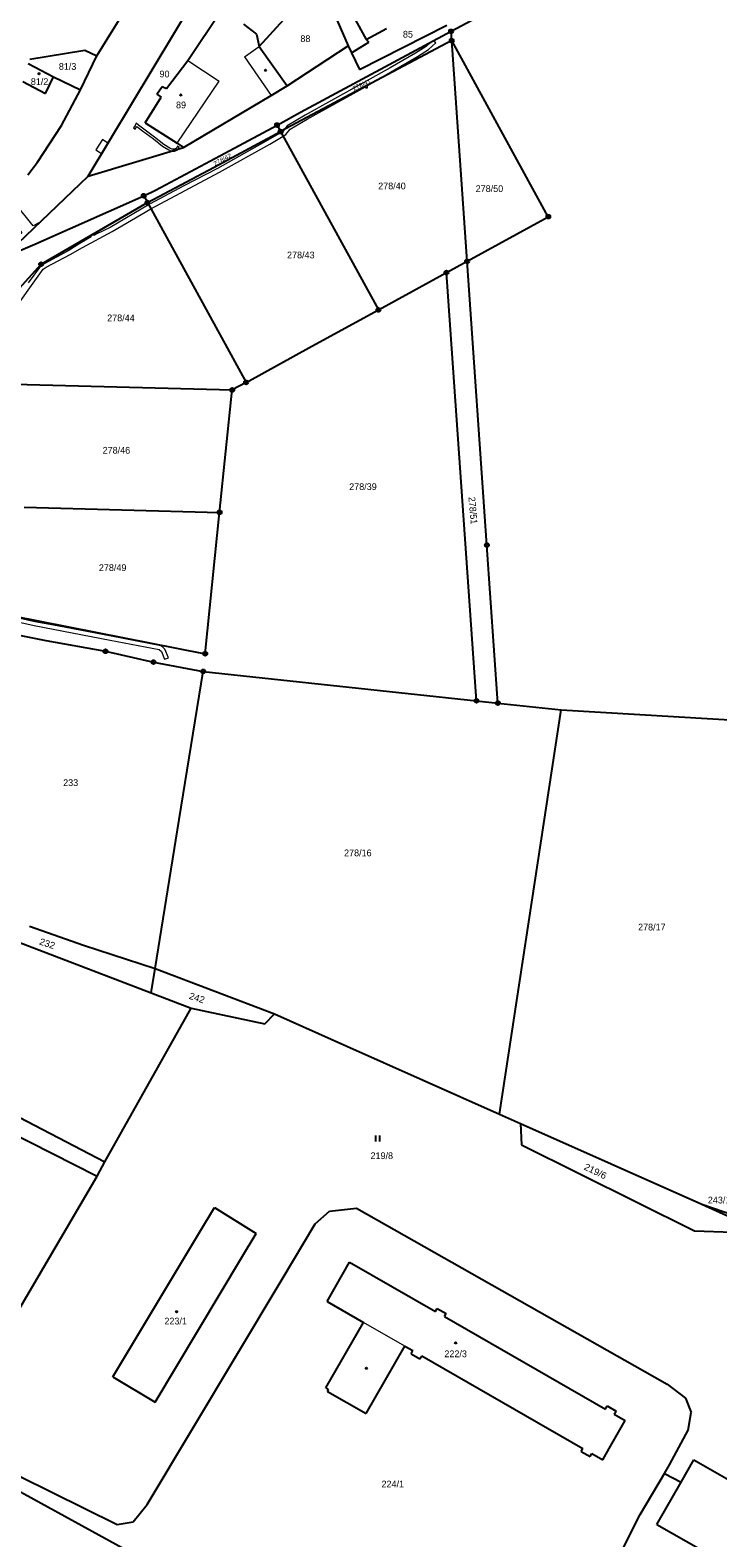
# Model space of a CAD drawing. Extents: x -633485 to -630509, y -1112692 to -1108818.
# Drawn here: x -631743.5 to -631569.8, y -1111932.7 to -1111552 of the extents above; entities that cross this region are included whole.
import ezdxf
from ezdxf.enums import TextEntityAlignment as Align

# ---------------------------------------------------------------- set-up
doc = ezdxf.new("R2010")
doc.units = 0
doc.header["$LTSCALE"] = 0.68
for name, color, linetype, lineweight in [('1', 7, 'Continuous', 25), ('13', 7, 'Continuous', 13), ('3', 7, 'Continuous', 25), ('4', 7, 'Continuous', 13), ('5', 7, 'Continuous', 25), ('8', 7, 'Continuous', 25)]:
    doc.layers.add(name, color=color, linetype=linetype, lineweight=lineweight)
doc.layers.add('2', color=7, linetype='Continuous')

msp = doc.modelspace()

# ---------------------------------------------------------------- linework, layer by layer
at = {"layer": '1'}
for p, q in [((-631726.65, -1111558.43), (-631645.19, -1111427.57)), ((-631637.17, -1111552.27), (-631591.93, -1111527.94)), ((-631685.62, -1111556.11), (-631670.36, -1111539.33)), ((-631670.36, -1111539.33), (-631663.19, -1111555.95)), ((-631665.55, -1111541.61), (-631658.58, -1111554.35)), ((-631728.81, -1111588.83), (-631701.37, -1111543.15)), ((-631703.67, -1111559.63), (-631695.16, -1111546.91)), ((-631689.61, -1111550.49), (-631686.3, -1111552.96)), ((-631686.3, -1111552.96), (-631685.62, -1111556.11)), ((-631675.15, -1111572.69), (-631637.17, -1111552.27)), ((-631660.31, -1111561.93), (-631638.26, -1111550.73)), ((-631658.58, -1111554.35), (-631653.51, -1111551.58)), ((-631658.58, -1111554.35), (-631657.97, -1111554.99)), ((-631637.01, -1111554.62), (-631637.17, -1111552.27)), ((-631743.57, -1111559.29), (-631729.66, -1111557.04)), ((-631729.66, -1111557.04), (-631726.65, -1111558.43)), ((-631685.62, -1111556.11), (-631678.57, -1111566.06)), ((-631637.01, -1111554.62), (-631680.21, -1111577.6)), ((-631678.57, -1111566.06), (-631663.19, -1111555.95)), ((-631663.19, -1111555.95), (-631662.33, -1111557.72)), ((-631662.33, -1111557.72), (-631657.97, -1111554.99)), ((-631662.33, -1111557.72), (-631660.31, -1111561.93)), ((-631633.12, -1111610.34), (-631637.01, -1111554.62)), ((-631612.61, -1111599.08), (-631637.01, -1111554.62)), ((-631743.97, -1111560.4), (-631737.55, -1111563.79)), ((-631730.72, -1111567.08), (-631726.65, -1111558.43)), ((-631709.03, -1111566.73), (-631703.67, -1111559.63)), ((-631745.34, -1111564.91), (-631739.54, -1111567.99)), ((-631739.54, -1111567.99), (-631737.55, -1111563.79)), ((-631737.55, -1111563.79), (-631730.72, -1111567.08)), ((-631735.51, -1111576.09), (-631730.72, -1111567.08)), ((-631714.38, -1111575.34), (-631710.39, -1111568.89)), ((-631711.46, -1111568.11), (-631710.14, -1111566.2)), ((-631711.46, -1111568.11), (-631710.39, -1111568.89)), ((-631710.14, -1111566.2), (-631709.03, -1111566.73)), ((-631704.71, -1111581.6), (-631682.58, -1111568.49)), ((-631682.58, -1111568.49), (-631678.57, -1111566.06)), ((-631681.12, -1111575.94), (-631675.15, -1111572.69)), ((-631741.6, -1111585.3), (-631735.51, -1111576.09)), ((-631714.38, -1111575.34), (-631706.32, -1111580.53)), ((-631681.12, -1111575.94), (-631680.21, -1111577.6)), ((-631706.32, -1111580.53), (-631704.71, -1111581.6)), ((-631697.03, -1111586.55), (-631680.21, -1111577.6)), ((-631680.21, -1111577.6), (-631655.5, -1111622.62)), ((-631728.81, -1111588.83), (-631704.71, -1111581.6)), ((-631744.02, -1111588.52), (-631741.6, -1111585.3)), ((-631713.85, -1111595.51), (-631697.03, -1111586.55)), ((-631750.36, -1111609.45), (-631728.81, -1111588.83)), ((-631714.78, -1111593.81), (-631711.8, -1111592.4)), ((-631742.31, -1111606), (-631714.78, -1111593.81)), ((-631714.78, -1111593.81), (-631713.85, -1111595.51)), ((-631713.85, -1111595.51), (-631688.93, -1111640.92)), ((-631633.12, -1111610.34), (-631612.61, -1111599.08)), ((-631750.36, -1111609.45), (-631742.31, -1111606)), ((-631638.34, -1111613.2), (-631633.12, -1111610.34)), ((-631628.12, -1111682.02), (-631633.12, -1111610.34)), ((-631655.5, -1111622.62), (-631638.34, -1111613.2)), ((-631630.76, -1111721.34), (-631638.34, -1111613.2)), ((-631672.29, -1111631.81), (-631655.5, -1111622.62)), ((-631688.93, -1111640.92), (-631672.29, -1111631.81)), ((-631750.72, -1111641.28), (-631692.44, -1111642.84)), ((-631688.93, -1111640.92), (-631692.44, -1111642.84)), ((-631695.61, -1111673.75), (-631692.44, -1111642.84)), ((-631744.99, -1111672.46), (-631695.61, -1111673.75)), ((-631699.26, -1111709.45), (-631695.61, -1111673.75)), ((-631625.34, -1111721.92), (-631628.12, -1111682.02)), ((-631747.8, -1111699.86), (-631699.26, -1111709.45)), ((-631748.3, -1111704.38), (-631739.51, -1111706.11)), ((-631739.51, -1111706.11), (-631724.44, -1111708.84)), ((-631724.44, -1111708.84), (-631712.31, -1111711.57)), ((-631712.31, -1111711.57), (-631699.75, -1111713.93)), ((-631705.81, -1111751.28), (-631699.75, -1111713.93)), ((-631699.75, -1111713.93), (-631630.76, -1111721.34)), ((-631630.76, -1111721.34), (-631625.34, -1111721.92)), ((-631625.34, -1111721.92), (-631609.33, -1111723.64)), ((-631624.97, -1111825.7), (-631609.33, -1111723.64)), ((-631609.33, -1111723.64), (-631547.66, -1111727.31)), ((-631711.92, -1111788.97), (-631705.81, -1111751.28)), ((-631772.03, -1111772.41), (-631712.92, -1111795.09)), ((-631743.6, -1111778.23), (-631729.98, -1111783.03)), ((-631729.98, -1111783.03), (-631711.92, -1111788.97)), ((-631712.92, -1111795.09), (-631711.92, -1111788.97)), ((-631711.92, -1111788.97), (-631681.77, -1111800.39)), ((-631712.92, -1111795.09), (-631702.83, -1111798.96)), ((-631724.6, -1111837.74), (-631702.83, -1111798.96)), ((-631702.83, -1111798.96), (-631684.21, -1111802.9)), ((-631684.21, -1111802.9), (-631681.77, -1111800.39)), ((-631681.77, -1111800.39), (-631663.5, -1111808.53)), ((-631783.6, -1111807.07), (-631724.6, -1111837.74)), ((-631663.5, -1111808.53), (-631624.97, -1111825.7)), ((-631624.97, -1111825.7), (-631619.66, -1111828.07)), ((-631619.66, -1111828.07), (-631573.85, -1111848.48)), ((-631619.66, -1111828.07), (-631619.42, -1111833.45)), ((-631749.29, -1111829.88), (-631726.57, -1111841.36)), ((-631619.42, -1111833.45), (-631575.68, -1111855.18)), ((-631726.57, -1111841.36), (-631724.6, -1111837.74)), ((-631755.72, -1111891.12), (-631726.57, -1111841.36)), ((-631700.57, -1111855.44), (-631696.88, -1111849.31)), ((-631696.88, -1111849.31), (-631686.35, -1111855.84)), ((-631671.46, -1111853.41), (-631667.89, -1111850.21)), ((-631667.89, -1111850.21), (-631661.04, -1111849.49)), ((-631661.04, -1111849.49), (-631585.75, -1111892.12)), ((-631573.85, -1111848.48), (-631565.87, -1111852.06)), ((-631573.85, -1111848.48), (-631565.74, -1111851.26)), ((-631679.83, -1111867.4), (-631671.46, -1111853.41)), ((-631575.68, -1111855.18), (-631566.02, -1111855.55)), ((-631722.57, -1111892.04), (-631700.57, -1111855.44)), ((-631690.06, -1111862.01), (-631686.35, -1111855.84)), ((-631711.93, -1111898.43), (-631690.06, -1111862.01)), ((-631668.47, -1111873.01), (-631662.78, -1111863.1)), ((-631662.78, -1111863.1), (-631641.09, -1111875.56)), ((-631713.9, -1111924.33), (-631679.83, -1111867.4)), ((-631668.47, -1111873.01), (-631659.25, -1111878.31)), ((-631641.09, -1111875.56), (-631640.64, -1111874.78)), ((-631640.64, -1111874.78), (-631638.41, -1111876.06)), ((-631638.86, -1111876.84), (-631638.41, -1111876.06)), ((-631638.86, -1111876.84), (-631598.21, -1111900.2)), ((-631668.78, -1111894.88), (-631659.25, -1111878.31)), ((-631658.64, -1111901.34), (-631648.87, -1111884.28)), ((-631648.87, -1111884.28), (-631646.82, -1111885.45)), ((-631647.27, -1111886.23), (-631646.82, -1111885.45)), ((-631647.27, -1111886.23), (-631645.04, -1111887.51)), ((-631645.04, -1111887.51), (-631644.59, -1111886.73)), ((-631644.59, -1111886.73), (-631603.86, -1111910.14)), ((-631722.57, -1111892.04), (-631711.93, -1111898.43)), ((-631585.75, -1111892.12), (-631582.59, -1111893.95)), ((-631668.78, -1111894.88), (-631668.12, -1111895.34)), ((-631668.37, -1111895.77), (-631668.12, -1111895.34)), ((-631668.37, -1111895.77), (-631658.64, -1111901.34)), ((-631582.59, -1111893.95), (-631577.99, -1111897.47)), ((-631598.21, -1111900.2), (-631597.76, -1111899.42)), ((-631597.76, -1111899.42), (-631595.51, -1111900.72)), ((-631595.95, -1111901.5), (-631595.51, -1111900.72)), ((-631577.99, -1111897.47), (-631576.58, -1111901.1)), ((-631597.25, -1111910.17), (-631593.18, -1111903.09)), ((-631595.95, -1111901.5), (-631593.18, -1111903.09)), ((-631577.27, -1111905.52), (-631576.58, -1111901.1)), ((-631582.02, -1111914.3), (-631577.27, -1111905.52)), ((-631604.31, -1111910.92), (-631603.86, -1111910.14)), ((-631604.31, -1111910.92), (-631602.06, -1111912.21)), ((-631602.06, -1111912.21), (-631601.61, -1111911.43)), ((-631601.61, -1111911.43), (-631598.88, -1111913.01)), ((-631598.88, -1111913.01), (-631597.25, -1111910.17)), ((-631583.31, -1111916.5), (-631582.02, -1111914.3)), ((-631579.07, -1111918.69), (-631575.84, -1111913.05)), ((-631575.84, -1111913.05), (-631491.08, -1111961.75)), ((-631746.13, -1111917.13), (-631721.5, -1111929.39)), ((-631589.4, -1111926.84), (-631583.31, -1111916.5)), ((-631585.18, -1111929.34), (-631579.07, -1111918.69)), ((-631583.31, -1111916.5), (-631579.07, -1111918.69)), ((-631747.56, -1111920.18), (-631631.76, -1111983.66)), ((-631717.42, -1111928.71), (-631713.9, -1111924.33)), ((-631621.1, -1111989.5), (-631589.4, -1111926.84)), ((-631721.5, -1111929.39), (-631717.42, -1111928.71)), ((-631585.18, -1111929.34), (-631570.43, -1111937.79))]:
    msp.add_line(p, q, dxfattribs=at)
for points in [[(-631711.8, -1111592.4), (-631697.91, -1111584.95), (-631681.12, -1111575.94)], [(-631750, -1111621.44), (-631740.68, -1111611.08), (-631713.85, -1111595.51)]]:
    msp.add_lwpolyline(points, dxfattribs=at)
at = {"layer": '13'}
for points in [[(-631678.88, -1111578.32), (-631677.84, -1111577.02), (-631673.49, -1111574.42), (-631658.8, -1111566.27), (-631658.76, -1111566.58), (-631658.27, -1111566.52), (-631658.28, -1111565.93), (-631645.65, -1111558.64), (-631642.83, -1111556.89), (-631641, -1111555.21), (-631641.54, -1111554.62), (-631642.26, -1111555.01), (-631643.43, -1111556.09), (-631646.17, -1111557.78), (-631652.54, -1111561.47), (-631659.17, -1111565.22), (-631667.39, -1111569.73), (-631674, -1111573.45), (-631678.56, -1111576.17), (-631679.68, -1111577.54), (-631680.08, -1111577.78), (-631680.21, -1111577.6), (-631679.59, -1111578.74)], [(-631708.17, -1111581.78), (-631709.72, -1111580.85), (-631712.05, -1111579), (-631714.76, -1111576.97), (-631716.13, -1111576), (-631716.71, -1111575.5), (-631716.98, -1111576.05), (-631717.39, -1111576.67), (-631716.97, -1111576.95), (-631716.56, -1111576.31), (-631715.06, -1111577.37), (-631712.35, -1111579.4), (-631710, -1111581.27), (-631708.41, -1111582.22), (-631707.8, -1111582.53), (-631707.76, -1111582.55), (-631706.98, -1111582.57), (-631706.33, -1111582.29), (-631706.14, -1111582.03), (-631705.81, -1111581.59), (-631706.21, -1111581.29), (-631706.36, -1111581.49), (-631706.65, -1111581.89), (-631707.08, -1111582.07), (-631707.64, -1111582.05)], [(-631723.8, -1111580.5), (-631725.17, -1111579.63), (-631726.84, -1111582.24), (-631725.4, -1111583.15)], [(-631680.62, -1111577.82), (-631680.5, -1111578.04), (-631683.48, -1111579.78), (-631696.18, -1111586.88), (-631704.69, -1111591.26), (-631713.19, -1111595.8), (-631713.57, -1111595.36), (-631713.85, -1111595.51), (-631712.97, -1111597.11), (-631695.66, -1111587.81), (-631682.97, -1111580.74), (-631679.59, -1111578.74), (-631680.21, -1111577.6), (-631680.35, -1111577.35), (-631680.76, -1111577.57)], [(-631761.74, -1111618.01), (-631750.36, -1111609.45), (-631740.93, -1111600.43), (-631742.73, -1111601.38), (-631747.13, -1111595.83), (-631748.39, -1111596.83), (-631749.72, -1111597.88), (-631745.53, -1111603.16), (-631761.93, -1111616.6)]]:
    msp.add_lwpolyline(points, close=True, dxfattribs=at)
for points in [[(-631748.95, -1111624.64), (-631743.11, -1111616.48), (-631740.15, -1111612.34), (-631739.4, -1111611.83), (-631733.39, -1111608.59), (-631730.25, -1111606.83), (-631722.76, -1111602.8), (-631712.97, -1111597.11), (-631713.85, -1111595.51), (-631714.02, -1111595.61), (-631713.61, -1111596.08), (-631723.29, -1111601.84), (-631726.63, -1111603.37), (-631727.41, -1111603.8), (-631727.75, -1111603.65), (-631728.19, -1111603.87), (-631728.04, -1111604.17), (-631730.89, -1111605.82), (-631733.87, -1111607.71), (-631739.78, -1111610.88), (-631740.85, -1111611.6), (-631743.93, -1111615.77)], [(-631746.57, -1111701.43), (-631742.46, -1111702.35), (-631723.23, -1111706.02), (-631710.86, -1111708.42), (-631710.27, -1111708.9), (-631709.5, -1111710.79), (-631708.55, -1111710.47), (-631709.42, -1111708.34), (-631709.93, -1111707.83), (-631710.5, -1111707.48), (-631723.03, -1111705.04), (-631736.65, -1111702.39), (-631742.26, -1111701.37), (-631745.95, -1111700.55)]]:
    msp.add_lwpolyline(points, dxfattribs=at)
at = {"layer": '3'}
for p, q in [((-631656.181, -1111832.61), (-631656.181, -1111831.11)), ((-631655.18, -1111832.61), (-631655.18, -1111831.11))]:
    msp.add_line(p, q, dxfattribs=at)
at = {"layer": '4'}
for p, q in [((-631689.33, -1111558.71), (-631685.62, -1111556.11)), ((-631703.67, -1111559.63), (-631695.7, -1111564.88)), ((-631689.33, -1111558.71), (-631682.58, -1111568.49)), ((-631706.32, -1111580.53), (-631695.7, -1111564.88)), ((-631648.87, -1111884.28), (-631659.25, -1111878.31))]:
    msp.add_line(p, q, dxfattribs=at)
at = {"layer": '5'}
for centre in [(-631684.0268, -1111562.0892), (-631741.2068, -1111562.9892), (-631705.4068, -1111568.3492), (-631706.4768, -1111875.6392), (-631636.0068, -1111883.4992), (-631658.5268, -1111889.9092)]:
    msp.add_circle(centre, 0.175, dxfattribs=at)
at = {"layer": '8'}
for centre, radius in [((-631637.17, -1111552.2699), 0.5), ((-631637.01, -1111554.6199), 0.5), ((-631637.17, -1111552.2699), 0.0303), ((-631637.01, -1111554.6199), 0.0303), ((-631681.12, -1111575.9399), 0.5), ((-631681.12, -1111575.9399), 0.0303), ((-631680.21, -1111577.5999), 0.5), ((-631680.21, -1111577.5999), 0.0303), ((-631714.78, -1111593.8099), 0.5), ((-631714.78, -1111593.8099), 0.0303), ((-631713.85, -1111595.5099), 0.5), ((-631713.85, -1111595.5099), 0.0303), ((-631612.61, -1111599.0799), 0.5), ((-631612.61, -1111599.0799), 0.0303), ((-631740.68, -1111611.0799), 0.5), ((-631740.68, -1111611.0799), 0.0303), ((-631633.12, -1111610.3399), 0.5), ((-631633.12, -1111610.3399), 0.0303), ((-631638.34, -1111613.1999), 0.5), ((-631638.34, -1111613.1999), 0.0303), ((-631655.5, -1111622.6199), 0.5), ((-631655.5, -1111622.6199), 0.0303), ((-631688.93, -1111640.9199), 0.5), ((-631688.93, -1111640.9199), 0.0303), ((-631692.44, -1111642.8399), 0.5), ((-631692.44, -1111642.8399), 0.0303), ((-631695.61, -1111673.7499), 0.5), ((-631695.61, -1111673.7499), 0.0303), ((-631628.12, -1111682.0199), 0.5), ((-631628.12, -1111682.0199), 0.0303), ((-631724.44, -1111708.8399), 0.5), ((-631724.44, -1111708.8399), 0.0303), ((-631699.26, -1111709.4499), 0.5), ((-631699.26, -1111709.4499), 0.0303), ((-631712.31, -1111711.5699), 0.5), ((-631712.31, -1111711.5699), 0.0303), ((-631699.75, -1111713.9299), 0.5), ((-631699.75, -1111713.9299), 0.0303), ((-631630.76, -1111721.3399), 0.5), ((-631630.76, -1111721.3399), 0.0303), ((-631625.34, -1111721.9199), 0.5), ((-631625.34, -1111721.9199), 0.0303)]:
    msp.add_circle(centre, radius, dxfattribs=at)

# ---------------------------------------------------------------- texts
at = {"layer": '2'}
for s, p in [('88', (-631675.21, -1111554.975)), ('85', (-631649.33, -1111553.855)), ('81/3', (-631736.22, -1111561.995)), ('81/2', (-631743.29, -1111565.825)), ('90', (-631710.79, -1111563.885)), ('89', (-631706.62, -1111571.715)), ('233', (-631735.12, -1111742.855)), ('278/16', (-631664.19, -1111760.595)), ('278/17', (-631589.95, -1111779.335)), ('219/8', (-631657.51, -1111837.075)), ('223/1', (-631709.56, -1111878.835)), ('222/3', (-631638.86, -1111887.105)), ('224/1', (-631654.73, -1111919.985))]:
    msp.add_text(s, height=1.7, dxfattribs=at).set_placement(p)
at = {"layer": '2', "width": 1.05}
for s, rotation, p in [('278/41', 25, (-631659.5067, -1111566.2704)), ('278/42', 28, (-631694.6194, -1111585.1383))]:
    msp.add_text(s, height=1.139, rotation=rotation, dxfattribs=at).set_placement(p, align=Align.CENTER)
at = {"layer": '2'}
for s, p in [('278/40', (-631652.1, -1111592.172)), ('278/50', (-631627.48, -1111592.842)), ('278/43', (-631675.11, -1111609.602)), ('278/44', (-631720.53, -1111625.492)), ('278/46', (-631721.68, -1111658.922)), ('278/39', (-631659.42, -1111668.112)), ('278/49', (-631722.63, -1111688.562)), ('243/1', (-631569.49, -1111848.275))]:
    msp.add_text(s, height=1.7, dxfattribs=at).set_placement(p, align=Align.CENTER)
msp.add_text('278/51', height=1.7, rotation=275, dxfattribs=at).set_placement((-631632.4836, -1111673.3589), align=Align.CENTER)
at = {"layer": '2', "width": 1.05}
for s, rotation, p in [('232', 342, (-631741.291, -1111782.844)), ('242', 342, (-631703.491, -1111796.554)), ('219/6', 334, (-631603.776, -1111839.611))]:
    msp.add_text(s, height=1.7, rotation=rotation, dxfattribs=at).set_placement(p)

doc.saveas('drawing.dxf')
